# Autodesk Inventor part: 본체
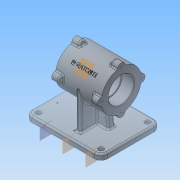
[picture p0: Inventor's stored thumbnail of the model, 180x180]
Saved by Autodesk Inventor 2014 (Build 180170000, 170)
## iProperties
Created: 2015-12
Part Number: 본체
Material: 일반
Document SubType Name: Modeling
Designer: nert
Density: 1 g/cm^3
Appearance: 기본값
Mass: 429.95 g
Surface Area: 814.906 cm^2
Volume: 429.95 cm^3
Author: nert
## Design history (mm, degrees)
sketch "스케치1"
  geometry: L1 (-70, 55)-(70, 55); L2 (70, 55)-(70, -55); L3 (70, -55)-(-70, -55); L4 (-70, -55)-(-70, 55); 3 further points
  constraints: 8 end point, 2 midpoint, 2 parallel, 1 horizontal, 1 horizontal alignment, 1 perpendicular, 1 vertical alignment
  dimensions: "d0" = 140 distance between parallel lines of L2 L4; "d1" = 110 distance between parallel lines of L3 L1
extrude "돌출1" new body sketch "스케치1" distance "d2" = 10; taper "d3" = 0 deg
node "작업 평면1"
node "작업 평면6"
  node "작업 평면5"
sketch "스케치5"
  geometry: C1 r 37 at (80, 55); 1 further point
  constraints: 1 centre point, 1 horizontal alignment
  dimensions: "d28" = 74 diameter of C1; "d29" = 80 distance of point (0, 55) C1.centre
extrude "돌출4" join sketch "스케치5" stored distance "d30" = 85; taper "d31" = 0 deg
sketch "스케치6"
  geometry: L1 (-52.5, 117)-(-52.5, 43) reference; L2 (-52.5, 80)-(32.5, 80); L3 (32.5, 43)-(32.5, 117) reference; L4 (-52.5, 103.5)-(-30.5, 103.5); L5 (-30.5, 103.5)-(-30.5, 80); L6 (-30.5, 101)-(10.5, 101); L7 (10.5, 101)-(10.5, 80); L8 (10.5, 101)-(10.5, 103.5); L9 (10.5, 103.5)-(32.5, 103.5); 1 further point
  constraints: 14 end point, 5 perpendicular, 5 point on line, 2 collinear, 2 midpoint, 1 horizontal
  dimensions: "d32" = 47 diameter of L4 L2; "d33" = 42 diameter of L6 L2; "d34" = 22 distance between parallel lines of L1 L5; "d35" = 22 distance between parallel lines of L3 L7
revolve "회전1" sketch "스케치6" stored, may be unused: angle "d36" = 90 deg
node "작업 평면7"
sketch "스케치7"
  geometry: L1 (-70, 55)-(70, 55) reference; L2 (70, 55)-(70, -55) reference; L3 (70, -55)-(-70, -55) reference; L4 (-70, -55)-(-70, 55) reference; L5 (14, 37)-(6, 37); L6 (6, 37)-(6, -37); L7 (6, -37)-(14, -37); L8 (14, -37)-(14, 37); 3 further points
  constraints: 8 end point, 3 midpoint, 2 parallel, 1 horizontal, 1 horizontal alignment, 1 perpendicular
  dimensions: "d38" = 8 distance between parallel lines of L6 L8; "d39" = 74 distance between parallel lines of L5 L7; "d40" = 80 distance from line of L4 point (10, 37); "d41" = 55 distance from line of point (6, 0) L3
extrude "돌출5" join sketch "스케치7" stored distance "d42" = 85; taper "d43" = 0 deg
node "작업 평면8"
node "작업 평면9"
node "작업 평면11"
node "작업 평면12"
sketch "스케치11"
  geometry: L1 (35, 6)-(-15, 6); L2 (-15, 6)-(-15, -6); L3 (-15, -6)-(35, -6); L4 (35, -6)-(35, 6); L5 (70, 55)-(70, -55) reference; 3 further points
  constraints: 8 end point, 2 midpoint, 2 parallel, 1 horizontal, 1 horizontal alignment, 1 perpendicular
  dimensions: "d58" = 35 distance between parallel lines of L5 L4; "d59" = 50 distance between parallel lines of L4 L2; "d60" = 12 distance between parallel lines of L1 L3
extrude "돌출7" join sketch "스케치11" stored distance "d61" = 12; taper "d62" = 0 deg
node "작업 평면13"
sketch "스케치12"
  geometry: L1 (-29, 0)-(-29, 33.49) reference; L2 (-8, 33.49)-(-29, 33.49) reference; L3 (21, 33.49)-(0, 33.49) reference; L4 (21, 0)-(21, 33.49) reference; L5 (-29, 0)-(-24.888, 33.49); L6 (-29, 0)-(-8, 0) reference; L7 (-8, 0)-(-8, 33.49) reference; L8 (21, 0)-(16.888, 33.49); L9 (0, 0)-(21, 0) reference; 1 further point
  constraints: 4 end point, 2 point on line
  dimensions: "d63" = 97 deg angle of L6 L5; "d64" = 97 deg angle of L9 L8
extrude "돌출8" cut sketch "스케치12" stored distance "d65" = 12; taper "d66" = 0 deg
node "작업 평면14"
sketch "스케치13"
  geometry: C1 r 23.5 at (0, 0) reference; C2 r 37 at (0, 0) reference; C3 r 23.5 at (0, 0); C4 r 37 at (0, 0); 1 further point
  constraints: 2 centre point, 2 coincident, 2 concentric
extrude "돌출9" join sketch "스케치13" stored distance "d67" = 50; taper "d68" = 0 deg
node "작업 평면15"
sketch "스케치14"
  geometry: A1 r 7 centre (-37, 0) between (-36.338, 6.969) and (-36.338, -6.969); A2 r 7 centre (0, -37) between (-6.969, -36.338) and (6.969, -36.338); A3 r 7 centre (37, 0) between (36.338, -6.969) and (36.338, 6.969); A4 r 7 centre (0, 37) between (6.969, 36.338) and (-6.969, 36.338); 2 further points
  constraints: 8 point on circle, 4 centre point, 3 equal radius, 2 horizontal alignment, 2 vertical alignment, 13 other
  dimensions: "d70" = 14 diameter of A1
extrude "돌출10" join sketch "스케치14" distance "d71" = 15; taper "d72" = 0 deg
node "작업 평면16"
node "작업 평면17"
node "작업 평면18"
sketch "스케치16"
  geometry: L1 (-52.5, 116.338)-(-52.5, 116.338) reference; L2 (-37.5, 116.338)-(-52.5, 116.338) reference; L3 (-37.5, 116.338)-(-37.5, 116.338) reference; L4 (-52.5, 116.338)-(-37.5, 116.338) reference; L5 (-52.5, 124)-(-37.5, 124) reference; L6 (-37.5, 117)-(17.5, 117) reference; L7 (-40.289, 124)-(-37.5, 124); L8 (-37.5, 116.338)-(-40.289, 124); L9 (-40.289, 124)-(-40.289, 124); L10 (-37.5, 116.338)-(-37.5, 124); 1 further point
  constraints: 8 end point, 2 point on line, 1 perpendicular
  dimensions: "d85" = 110 deg angle of L2 L8
extrude "돌출11" cut sketch "스케치16" stored distance "d86" = 15; taper "d87" = 0 deg
node "작업 평면19"
node "작업 평면20"
sketch "스케치17"
  geometry: L1 (-70, -55)-(70, -55) reference; L2 (-70, 55)-(-70, -55) reference; C1 r 4 at (-58, -43); 1 further point
  constraints: 1 centre point
  dimensions: "d92" = 12 distance from line of L1 C1.centre; "d93" = 12 distance from line of C1.centre L2; "d94" = 8 diameter of C1
extrude "돌출12" cut sketch "스케치17" distance "d95" = 15; taper "d96" = 0 deg
node "작업 평면21"
node "작업 평면22"
fillet "모깎기2" dims "d98" = 3
node "작업 평면23"
sketch "스케치18"
  geometry: C1 r 37 at (80, 55); C2 r 21 at (80, 55) reference; C3 r 23.5 at (80, 55) reference; C4 r 23.5 at (80, 55); A1 r 37 centre (80, 55) between (86.969, 18.662) and (116.338, 48.031) reference; 1 further point
  constraints: 2 centre point, 2 coincident, 1 concentric
  dimensions: "d99" = 74 diameter of C1
extrude "돌출13" join sketch "스케치18" stored distance "d100" = 85; taper "d101" = 0 deg
fillet "모깎기3" dims "d102" = 3
node "작업 평면29"
node "작업 평면31"
sketch "스케치20"
  geometry: C1 r 23.5 at (-80, 55) reference; A1 r 7 centre (-43, 55) between (-41.761, 48.111) and (-41.761, 61.889) reference; A2 r 3 centre (-41.23, 64.842) between (-44.138, 64.104) and (-41.761, 61.889) reference; A3 r 37 centre (-80, 55) between (-44.138, 64.104) and (-70.896, 90.862) reference; A4 r 3 centre (-70.158, 93.77) between (-73.111, 93.239) and (-70.896, 90.862) reference; A5 r 7 centre (-80, 92) between (-73.111, 93.239) and (-86.889, 93.239) reference; A6 r 3 centre (-89.842, 93.77) between (-89.104, 90.862) and (-86.889, 93.239) reference; A7 r 37 centre (-80, 55) between (-89.104, 90.862) and (-115.862, 64.104) reference; A8 r 3 centre (-118.77, 64.842) between (-118.239, 61.889) and (-115.862, 64.104) reference; A9 r 7 centre (-117, 55) between (-118.239, 61.889) and (-118.239, 48.111) reference; A10 r 3 centre (-118.77, 45.158) between (-115.862, 45.896) and (-118.239, 48.111) reference; A11 r 37 centre (-80, 55) between (-115.862, 45.896) and (-89.104, 19.137) reference; A12 r 3 centre (-89.842, 16.23) between (-86.889, 16.761) and (-89.104, 19.137) reference; A13 r 7 centre (-80, 18) between (-86.889, 16.761) and (-73.111, 16.761) reference; A14 r 3 centre (-70.158, 16.23) between (-70.896, 19.137) and (-73.111, 16.761) reference; A15 r 37 centre (-80, 55) between (-70.896, 19.137) and (-44.138, 45.896) reference; A16 r 3 centre (-41.23, 45.158) between (-41.761, 48.111) and (-44.138, 45.896) reference; 4 further points
  constraints: 3 coincident
hole "구멍3" sketch "스케치20" at (-80, 92), (-43, 55), (-80, 18) diameter "d115" = 3.242; stored, may be unused: countersink angle "d119" = 90 deg, drill point angle "d121" = 118 deg; dims "d116" = 9, "d117" = 4, "d118" = 2, "d120" = 11
fillet "모깎기4" dims "d122" = 12
fillet "모깎기5" dims "d123" = 3
chamfer "모따기1" distance "d124" = 1; stored, may be unused: second distance "d125" = 2, angle "d126" = 45 deg
chamfer "모따기2" distance "d127" = 1; stored, may be unused: second distance "d128" = 2, angle "d129" = 45 deg
node "작업 평면32"
sketch "스케치21"
  geometry: L1 (-80, 55)-(-106.163, 28.837); L2 (-80, 11)-(-80, 99); C1 r 24.5 at (-80, 55) reference; A1 r 37 centre (-80, 55) between (-70.896, 19.137) and (-44.138, 45.896) reference; A2 r 3 centre (-70.158, 16.23) between (-70.896, 19.137) and (-73.111, 16.761) reference; A3 r 7 centre (-80, 18) between (-86.889, 16.761) and (-73.111, 16.761) reference; A4 r 3 centre (-89.842, 16.23) between (-86.889, 16.761) and (-89.104, 19.137) reference; A5 r 37 centre (-80, 55) between (-115.862, 45.896) and (-89.104, 19.137) reference; A6 r 3 centre (-118.77, 45.158) between (-115.862, 45.896) and (-118.239, 48.111) reference; A7 r 7 centre (-117, 55) between (-118.239, 61.889) and (-118.239, 48.111) reference; A8 r 3 centre (-118.77, 64.842) between (-118.239, 61.889) and (-115.862, 64.104) reference; A9 r 37 centre (-80, 55) between (-89.104, 90.862) and (-115.862, 64.104) reference; A10 r 3 centre (-89.842, 93.77) between (-89.104, 90.862) and (-86.889, 93.239) reference; A11 r 7 centre (-80, 92) between (-73.111, 93.239) and (-86.889, 93.239) reference; A12 r 3 centre (-70.158, 93.77) between (-73.111, 93.239) and (-70.896, 90.862) reference; A13 r 37 centre (-80, 55) between (-44.138, 64.104) and (-70.896, 90.862) reference; A14 r 3 centre (-41.23, 64.842) between (-44.138, 64.104) and (-41.761, 61.889) reference; A15 r 7 centre (-43, 55) between (-41.761, 48.111) and (-41.761, 61.889) reference; A16 r 3 centre (-41.23, 45.158) between (-41.761, 48.111) and (-44.138, 45.896) reference; 1 further point
  constraints: 4 end point, 3 point on circle
  dimensions: "d133" = 45 deg angle of L2 L1
  node "투영된 루프9"
node "작업 평면30"
fillet "모깎기6" dims "d137" = 3
sketch "스케치24"
  geometry: 1 further point
node "작업 평면34"
sketch "스케치25"
  geometry: L1 (-42.5, 18.921)-(-42.5, -18.921) reference; L2 (42.5, -18.921)-(42.5, 18.921) reference; 3 further points
  constraints: 1 horizontal alignment, 1 midpoint, 1 other
  dimensions: "d147" = 42.5 distance from line of point (0, 0) L1
feature "엠보싱2" sketch "스케치25" dims "d148" = 0.5, "d149" = 0
node "작업 평면35"
sketch "스케치26"
  geometry: A1 r 7 centre (-117, 55) between (-118.239, 61.889) and (-118.239, 48.111) reference; 2 further points
  constraints: 1 coincident
hole "구멍5" sketch "스케치26" at (-117, 55) diameter "d151" = 3.242; stored, may be unused: countersink angle "d155" = 90 deg, drill point angle "d157" = 118 deg; dims "d152" = 9, "d153" = 4, "d154" = 2, "d156" = 11
node "작업 평면36"
fillet "모깎기7" dims "d158" = 0.3
node "솔리드1"
mirror "대칭2"
pattern_circular "원형 패턴1" dims angle "d89" = 360 deg
mirror "대칭4"
mirror "대칭5"
mirror "대칭6"
pattern_circular "원형 패턴2" dims angle "d112" = 360 deg
mirror "대칭8"
node "투영된 루프3"
node "투영된 루프6"
node "투영된 루프7"
node "투영된 루프8"
other parameters: "d4" = 0, "d7" = 8, "d8" = 12, "d26" = 0, "d37" = 0, "d44" = 0, "d57" = 0, "d69" = 0, "d73" = 0, "d91" = 0, "d146" = 0.5, "d150" = 0
